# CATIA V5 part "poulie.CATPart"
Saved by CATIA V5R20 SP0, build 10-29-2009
Part number: 5
Bounding box of the stored display mesh (mm): x -75 to 75, y -75 to 75, z 0 to 20
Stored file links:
  C:\Users\halimelbaba\Documents\cmv\projet\poulie.CATPart
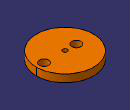
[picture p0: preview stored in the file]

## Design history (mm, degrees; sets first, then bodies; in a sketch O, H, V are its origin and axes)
Body1 (main body)
  Sketch1 on xy-plane, origin (0, 0, 0), H (1, 0, 0), V (0, 1, 0)
    circle A1 centre (0, 0) radius 75
    radius A1 = 75
  Pad1: profile Sketch1, direction (0, 0, 1), length 20
  Sketch2 on end face of Pad1, origin (0, 0, 20), H (1, 0, 0), V (0, 1, 0)
    point P1 (55, 0)
    distance P1 V = 55
    distance P1 H = 0
  Hole1: placed by Sketch2, at (55, 0, 20) direction (0, 0, -1), diameter 24, up to start face of Pad1
  Sketch3 on end face of Pad1, origin (0, 0, 20), H (1, 0, 0), V (0, 1, 0)
    point P1 (-30, 0)
    reference projected point E1 (55, 0) from axis of face of Hole1
    distance E1 P1 = 85
  Hole2: placed by Sketch3, at (-30, 0, 20) direction (0, 0, -1), diameter 24, up to start face of Pad1
  Sketch4 on end face of Pad1, origin (0, 0, 20), H (1, 0, 0), V (0, 1, 0)
    point P1 (0, 0)
    reference projected circle E1 centre (0, 0) radius 75 from edge [face of Pad1 from Sketch1.A1 | end face of Pad1]
    concentricity: P1 E1
  Hole3: placed by Sketch4, at (0, 0, 20) direction (0, 0, -1), diameter 12, up to start face of Pad1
